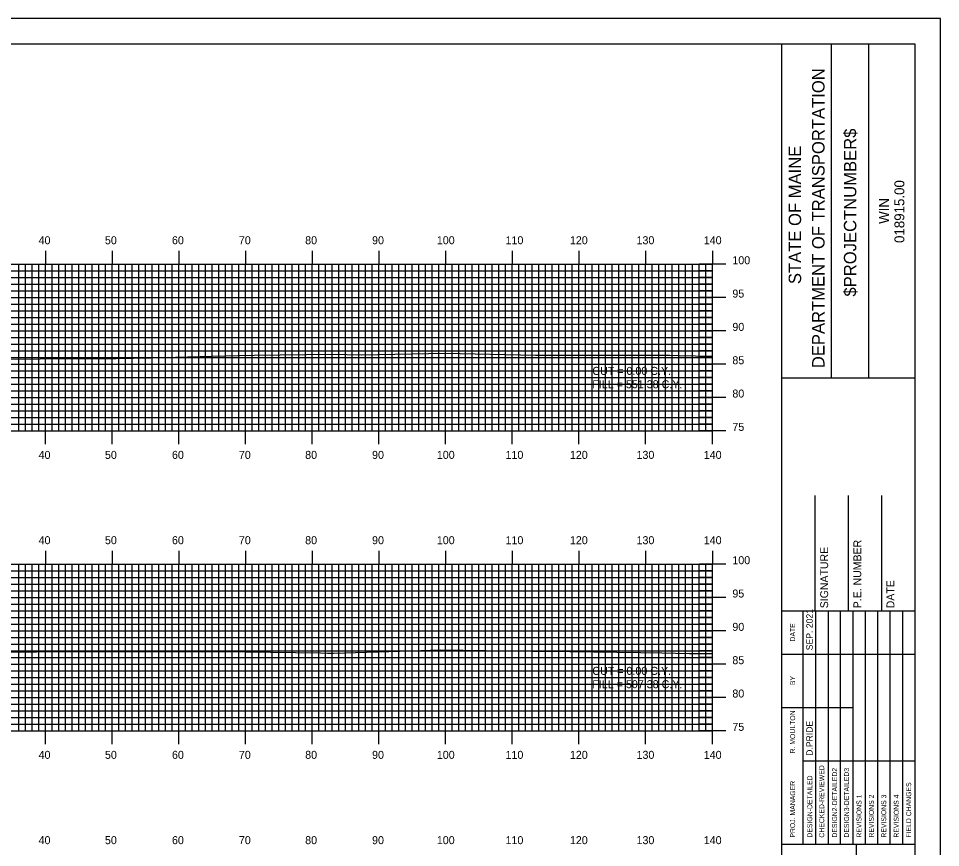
# Model space of a CAD drawing. Extents: x 1666 to 2009, y -1658 to -1438.
# Drawn here: x 1867.6 to 2005.9, y -1562.1 to -1437.7 of the extents above; entities that cross this region are included whole.
import ezdxf

# ---------------------------------------------------------------- set-up
doc = ezdxf.new("R2010")
doc.units = 0
for name, color, linetype in [('BORDER', 7, 'Continuous'), ('D_Text_Standard', 7, 'Continuous'), ('H_V ANNOTATION', 7, 'Continuous'), ('MAJOR', 7, 'Continuous'), ('MINOR', 7, 'Continuous'), ('PLOT BOUNDARY', 7, 'Continuous'), ('S_Roadway_Centerline', 7, 'Continuous')]:
    doc.layers.add(name, color=color, linetype=linetype)

msp = doc.modelspace()

# ---------------------------------------------------------------- linework, layer by layer
at = {"layer": 'BORDER'}
for p, q in [((1982.07, -1651.6), (1982.07, -1441.6)), ((1989.53, -1491.61), (1989.53, -1441.61)), ((1995.12, -1491.61), (1995.12, -1441.61)), ((1982.08, -1491.62), (2002.07, -1491.62)), ((1987.07, -1526.6), (1987.07, -1509.3)), ((1992.07, -1526.6), (1992.07, -1509.3)), ((1997.07, -1526.6), (1997.07, -1509.3)), ((1982.07, -1526.6), (2002.07, -1526.6)), ((1982.07, -1561.6), (2002.07, -1561.6)), ((1993.26, -1631.6), (1993.26, -1561.6))]:
    msp.add_line(p, q, dxfattribs=at)
msp.add_lwpolyline([(1682.07, -1651.6), (2002.07, -1651.6), (2002.07, -1441.6), (1682.07, -1441.6)], close=True, dxfattribs=at)
for points in [[(1985.3, -1533.1), (1985.3, -1526.6)], [(1987.17, -1561.59), (1987.17, -1526.6)], [(1989.03, -1526.6), (1989.03, -1561.59)], [(1990.9, -1561.59), (1990.9, -1526.6)], [(1992.76, -1561.59), (1992.76, -1526.6)], [(1994.62, -1561.59), (1994.62, -1526.6)], [(1996.49, -1561.59), (1996.49, -1526.6)], [(1998.35, -1561.59), (1998.35, -1526.6)], [(2000.21, -1561.59), (2000.21, -1526.6)], [(1985.31, -1561.59), (1985.31, -1528.01)], [(1982.07, -1533.1), (2002.07, -1533.1)], [(1982.07, -1541.1), (1985.31, -1541.1)], [(1985.3, -1541.1), (1992.76, -1541.1)], [(1985.3, -1549.1), (2002.07, -1549.1)]]:
    msp.add_lwpolyline(points, dxfattribs=at)
at = {"layer": 'MAJOR'}
for p, q in [((1871.67, -1472.6), (1871.67, -1474.6)), ((1881.67, -1472.6), (1881.67, -1474.6)), ((1891.67, -1472.6), (1891.67, -1474.6)), ((1901.67, -1472.6), (1901.67, -1474.6)), ((1911.67, -1472.6), (1911.67, -1474.6)), ((1921.67, -1472.6), (1921.67, -1474.6)), ((1931.67, -1472.6), (1931.67, -1474.6)), ((1941.67, -1472.6), (1941.67, -1474.6)), ((1951.67, -1472.6), (1951.67, -1474.6)), ((1961.67, -1472.6), (1961.67, -1474.6)), ((1971.67, -1472.6), (1971.67, -1474.6)), ((1691.67, -1474.6), (1971.67, -1474.6)), ((1691.67, -1474.6), (1971.67, -1474.6)), ((1871.67, -1499.6), (1871.67, -1474.6)), ((1881.67, -1499.6), (1881.67, -1474.6)), ((1891.67, -1499.6), (1891.67, -1474.6)), ((1901.67, -1499.6), (1901.67, -1474.6)), ((1911.67, -1499.6), (1911.67, -1474.6)), ((1921.67, -1499.6), (1921.67, -1474.6)), ((1931.67, -1499.6), (1931.67, -1474.6)), ((1941.67, -1499.6), (1941.67, -1474.6)), ((1951.67, -1499.6), (1951.67, -1474.6)), ((1961.67, -1499.6), (1961.67, -1474.6)), ((1973.68, -1474.6), (1969.67, -1474.6)), ((1971.67, -1499.6), (1971.67, -1474.6)), ((1971.67, -1499.6), (1971.67, -1474.6)), ((1691.67, -1479.6), (1971.67, -1479.6)), ((1973.68, -1479.6), (1969.67, -1479.6)), ((1691.67, -1484.6), (1971.67, -1484.6)), ((1973.68, -1484.6), (1969.67, -1484.6)), ((1691.67, -1489.6), (1971.67, -1489.6)), ((1973.68, -1489.6), (1969.67, -1489.6)), ((1691.67, -1494.6), (1971.67, -1494.6)), ((1973.68, -1494.6), (1969.67, -1494.6)), ((1691.67, -1499.6), (1971.67, -1499.6)), ((1691.67, -1499.6), (1971.67, -1499.6)), ((1871.67, -1501.61), (1871.67, -1499.6)), ((1881.67, -1501.61), (1881.67, -1499.6)), ((1891.67, -1501.61), (1891.67, -1499.6)), ((1901.67, -1501.61), (1901.67, -1499.6)), ((1911.67, -1501.61), (1911.67, -1499.6)), ((1921.67, -1501.61), (1921.67, -1499.6)), ((1931.67, -1501.61), (1931.67, -1499.6)), ((1941.67, -1501.61), (1941.67, -1499.6)), ((1951.67, -1501.61), (1951.67, -1499.6)), ((1961.67, -1501.61), (1961.67, -1499.6)), ((1973.68, -1499.6), (1969.67, -1499.6)), ((1971.67, -1501.61), (1971.67, -1499.6)), ((1871.67, -1517.6), (1871.67, -1519.6)), ((1881.67, -1517.6), (1881.67, -1519.6)), ((1891.67, -1517.6), (1891.67, -1519.6)), ((1901.67, -1517.6), (1901.67, -1519.6)), ((1911.67, -1517.6), (1911.67, -1519.6)), ((1921.67, -1517.6), (1921.67, -1519.6)), ((1931.67, -1517.6), (1931.67, -1519.6)), ((1941.67, -1517.6), (1941.67, -1519.6)), ((1951.67, -1517.6), (1951.67, -1519.6)), ((1961.67, -1517.6), (1961.67, -1519.6)), ((1971.67, -1517.6), (1971.67, -1519.6)), ((1691.67, -1519.6), (1971.67, -1519.6)), ((1691.67, -1519.6), (1971.67, -1519.6)), ((1871.67, -1544.6), (1871.67, -1519.6)), ((1881.67, -1544.6), (1881.67, -1519.6)), ((1891.67, -1544.6), (1891.67, -1519.6)), ((1901.67, -1544.6), (1901.67, -1519.6)), ((1911.67, -1544.6), (1911.67, -1519.6)), ((1921.67, -1544.6), (1921.67, -1519.6)), ((1931.67, -1544.6), (1931.67, -1519.6)), ((1941.67, -1544.6), (1941.67, -1519.6)), ((1951.67, -1544.6), (1951.67, -1519.6)), ((1961.67, -1544.6), (1961.67, -1519.6)), ((1973.68, -1519.6), (1969.67, -1519.6)), ((1971.67, -1544.6), (1971.67, -1519.6)), ((1971.67, -1544.6), (1971.67, -1519.6)), ((1691.67, -1524.6), (1971.67, -1524.6)), ((1973.68, -1524.6), (1969.67, -1524.6)), ((1691.67, -1529.6), (1971.67, -1529.6)), ((1973.68, -1529.6), (1969.67, -1529.6)), ((1691.67, -1534.6), (1971.67, -1534.6)), ((1973.68, -1534.6), (1969.67, -1534.6)), ((1691.67, -1539.6), (1971.67, -1539.6)), ((1973.68, -1539.6), (1969.67, -1539.6)), ((1691.67, -1544.6), (1971.67, -1544.6)), ((1691.67, -1544.6), (1971.67, -1544.6)), ((1871.67, -1546.61), (1871.67, -1544.6)), ((1881.67, -1546.61), (1881.67, -1544.6)), ((1891.67, -1546.61), (1891.67, -1544.6)), ((1901.67, -1546.61), (1901.67, -1544.6)), ((1911.67, -1546.61), (1911.67, -1544.6)), ((1921.67, -1546.61), (1921.67, -1544.6)), ((1931.67, -1546.61), (1931.67, -1544.6)), ((1941.67, -1546.61), (1941.67, -1544.6)), ((1951.67, -1546.61), (1951.67, -1544.6)), ((1961.67, -1546.61), (1961.67, -1544.6)), ((1973.68, -1544.6), (1969.67, -1544.6)), ((1971.67, -1546.61), (1971.67, -1544.6))]:
    msp.add_line(p, q, dxfattribs=at)
at = {"layer": 'MINOR'}
for p, q in [((1867.67, -1499.6), (1867.67, -1474.6)), ((1868.67, -1499.6), (1868.67, -1474.6)), ((1869.67, -1499.6), (1869.67, -1474.6)), ((1870.67, -1499.6), (1870.67, -1474.6)), ((1872.67, -1499.6), (1872.67, -1474.6)), ((1873.67, -1499.6), (1873.67, -1474.6)), ((1874.67, -1499.6), (1874.67, -1474.6)), ((1875.67, -1499.6), (1875.67, -1474.6)), ((1876.67, -1499.6), (1876.67, -1474.6)), ((1877.67, -1499.6), (1877.67, -1474.6)), ((1878.67, -1499.6), (1878.67, -1474.6)), ((1879.67, -1499.6), (1879.67, -1474.6)), ((1880.67, -1499.6), (1880.67, -1474.6)), ((1882.67, -1499.6), (1882.67, -1474.6)), ((1883.67, -1499.6), (1883.67, -1474.6)), ((1884.67, -1499.6), (1884.67, -1474.6)), ((1885.67, -1499.6), (1885.67, -1474.6)), ((1886.67, -1499.6), (1886.67, -1474.6)), ((1887.67, -1499.6), (1887.67, -1474.6)), ((1888.67, -1499.6), (1888.67, -1474.6)), ((1889.67, -1499.6), (1889.67, -1474.6)), ((1890.67, -1499.6), (1890.67, -1474.6)), ((1892.67, -1499.6), (1892.67, -1474.6)), ((1893.67, -1499.6), (1893.67, -1474.6)), ((1894.67, -1499.6), (1894.67, -1474.6)), ((1895.67, -1499.6), (1895.67, -1474.6)), ((1896.67, -1499.6), (1896.67, -1474.6)), ((1897.67, -1499.6), (1897.67, -1474.6)), ((1898.67, -1499.6), (1898.67, -1474.6)), ((1899.67, -1499.6), (1899.67, -1474.6)), ((1900.67, -1499.6), (1900.67, -1474.6)), ((1902.67, -1499.6), (1902.67, -1474.6)), ((1903.67, -1499.6), (1903.67, -1474.6)), ((1904.67, -1499.6), (1904.67, -1474.6)), ((1905.67, -1499.6), (1905.67, -1474.6)), ((1906.67, -1499.6), (1906.67, -1474.6)), ((1907.67, -1499.6), (1907.67, -1474.6)), ((1908.67, -1499.6), (1908.67, -1474.6)), ((1909.67, -1499.6), (1909.67, -1474.6)), ((1910.67, -1499.6), (1910.67, -1474.6)), ((1912.67, -1499.6), (1912.67, -1474.6)), ((1913.67, -1499.6), (1913.67, -1474.6)), ((1914.67, -1499.6), (1914.67, -1474.6)), ((1915.67, -1499.6), (1915.67, -1474.6)), ((1916.67, -1499.6), (1916.67, -1474.6)), ((1917.67, -1499.6), (1917.67, -1474.6)), ((1918.67, -1499.6), (1918.67, -1474.6)), ((1919.67, -1499.6), (1919.67, -1474.6)), ((1920.67, -1499.6), (1920.67, -1474.6)), ((1922.67, -1499.6), (1922.67, -1474.6)), ((1923.67, -1499.6), (1923.67, -1474.6)), ((1924.67, -1499.6), (1924.67, -1474.6)), ((1925.67, -1499.6), (1925.67, -1474.6)), ((1926.67, -1499.6), (1926.67, -1474.6)), ((1927.67, -1499.6), (1927.67, -1474.6)), ((1928.67, -1499.6), (1928.67, -1474.6)), ((1929.67, -1499.6), (1929.67, -1474.6)), ((1930.67, -1499.6), (1930.67, -1474.6)), ((1932.67, -1499.6), (1932.67, -1474.6)), ((1933.67, -1499.6), (1933.67, -1474.6)), ((1934.67, -1499.6), (1934.67, -1474.6)), ((1935.67, -1499.6), (1935.67, -1474.6)), ((1936.67, -1499.6), (1936.67, -1474.6)), ((1937.67, -1499.6), (1937.67, -1474.6)), ((1938.67, -1499.6), (1938.67, -1474.6)), ((1939.67, -1499.6), (1939.67, -1474.6)), ((1940.67, -1499.6), (1940.67, -1474.6)), ((1942.67, -1499.6), (1942.67, -1474.6)), ((1943.67, -1499.6), (1943.67, -1474.6)), ((1944.67, -1499.6), (1944.67, -1474.6)), ((1945.67, -1499.6), (1945.67, -1474.6)), ((1946.67, -1499.6), (1946.67, -1474.6)), ((1947.67, -1499.6), (1947.67, -1474.6)), ((1948.67, -1499.6), (1948.67, -1474.6)), ((1949.67, -1499.6), (1949.67, -1474.6)), ((1950.67, -1499.6), (1950.67, -1474.6)), ((1952.67, -1499.6), (1952.67, -1474.6)), ((1953.67, -1499.6), (1953.67, -1474.6)), ((1954.67, -1499.6), (1954.67, -1474.6)), ((1955.67, -1499.6), (1955.67, -1474.6)), ((1956.67, -1499.6), (1956.67, -1474.6)), ((1957.67, -1499.6), (1957.67, -1474.6)), ((1958.67, -1499.6), (1958.67, -1474.6)), ((1959.67, -1499.6), (1959.67, -1474.6)), ((1960.67, -1499.6), (1960.67, -1474.6)), ((1962.67, -1499.6), (1962.67, -1474.6)), ((1963.67, -1499.6), (1963.67, -1474.6)), ((1964.67, -1499.6), (1964.67, -1474.6)), ((1965.67, -1499.6), (1965.67, -1474.6)), ((1966.67, -1499.6), (1966.67, -1474.6)), ((1967.67, -1499.6), (1967.67, -1474.6)), ((1968.67, -1499.6), (1968.67, -1474.6)), ((1969.67, -1499.6), (1969.67, -1474.6)), ((1970.67, -1499.6), (1970.67, -1474.6)), ((1691.67, -1475.6), (1971.67, -1475.6)), ((1971.67, -1475.6), (1969.67, -1475.6)), ((1691.67, -1476.6), (1971.67, -1476.6)), ((1691.67, -1477.6), (1971.67, -1477.6)), ((1971.67, -1476.6), (1969.67, -1476.6)), ((1971.67, -1477.6), (1969.67, -1477.6)), ((1691.67, -1478.6), (1971.67, -1478.6)), ((1971.67, -1478.6), (1969.67, -1478.6)), ((1691.67, -1480.6), (1971.67, -1480.6)), ((1971.67, -1480.6), (1969.67, -1480.6)), ((1691.67, -1481.6), (1971.67, -1481.6)), ((1971.67, -1481.6), (1969.67, -1481.6)), ((1691.67, -1482.6), (1971.67, -1482.6)), ((1971.67, -1482.6), (1969.67, -1482.6)), ((1691.67, -1483.6), (1971.67, -1483.6)), ((1971.67, -1483.6), (1969.67, -1483.6)), ((1691.67, -1485.6), (1971.67, -1485.6)), ((1971.67, -1485.6), (1969.67, -1485.6)), ((1691.67, -1486.6), (1971.67, -1486.6)), ((1691.67, -1487.6), (1971.67, -1487.6)), ((1971.67, -1486.6), (1969.67, -1486.6)), ((1971.67, -1487.6), (1969.67, -1487.6)), ((1691.67, -1488.6), (1971.67, -1488.6)), ((1971.67, -1488.6), (1969.67, -1488.6)), ((1691.67, -1490.6), (1971.67, -1490.6)), ((1691.67, -1491.6), (1971.67, -1491.6)), ((1971.67, -1490.6), (1969.67, -1490.6)), ((1971.67, -1491.6), (1969.67, -1491.6)), ((1691.67, -1492.6), (1971.67, -1492.6)), ((1971.67, -1492.6), (1969.67, -1492.6)), ((1691.67, -1493.6), (1971.67, -1493.6)), ((1971.67, -1493.6), (1969.67, -1493.6)), ((1691.67, -1495.6), (1971.67, -1495.6)), ((1971.67, -1495.6), (1969.67, -1495.6)), ((1691.67, -1496.6), (1971.67, -1496.6)), ((1971.67, -1496.6), (1969.67, -1496.6)), ((1691.67, -1497.6), (1971.67, -1497.6)), ((1691.67, -1498.6), (1971.67, -1498.6)), ((1971.67, -1497.6), (1969.67, -1497.6)), ((1971.67, -1498.6), (1969.67, -1498.6)), ((1691.67, -1520.6), (1971.67, -1520.6)), ((1867.67, -1544.6), (1867.67, -1519.6)), ((1868.67, -1544.6), (1868.67, -1519.6)), ((1869.67, -1544.6), (1869.67, -1519.6)), ((1870.67, -1544.6), (1870.67, -1519.6)), ((1872.67, -1544.6), (1872.67, -1519.6)), ((1873.67, -1544.6), (1873.67, -1519.6)), ((1874.67, -1544.6), (1874.67, -1519.6)), ((1875.67, -1544.6), (1875.67, -1519.6)), ((1876.67, -1544.6), (1876.67, -1519.6)), ((1877.67, -1544.6), (1877.67, -1519.6)), ((1878.67, -1544.6), (1878.67, -1519.6)), ((1879.67, -1544.6), (1879.67, -1519.6)), ((1880.67, -1544.6), (1880.67, -1519.6)), ((1882.67, -1544.6), (1882.67, -1519.6)), ((1883.67, -1544.6), (1883.67, -1519.6)), ((1884.67, -1544.6), (1884.67, -1519.6)), ((1885.67, -1544.6), (1885.67, -1519.6)), ((1886.67, -1544.6), (1886.67, -1519.6)), ((1887.67, -1544.6), (1887.67, -1519.6)), ((1888.67, -1544.6), (1888.67, -1519.6)), ((1889.67, -1544.6), (1889.67, -1519.6)), ((1890.67, -1544.6), (1890.67, -1519.6)), ((1892.67, -1544.6), (1892.67, -1519.6)), ((1893.67, -1544.6), (1893.67, -1519.6)), ((1894.67, -1544.6), (1894.67, -1519.6)), ((1895.67, -1544.6), (1895.67, -1519.6)), ((1896.67, -1544.6), (1896.67, -1519.6)), ((1897.67, -1544.6), (1897.67, -1519.6)), ((1898.67, -1544.6), (1898.67, -1519.6)), ((1899.67, -1544.6), (1899.67, -1519.6)), ((1900.67, -1544.6), (1900.67, -1519.6)), ((1902.67, -1544.6), (1902.67, -1519.6)), ((1903.67, -1544.6), (1903.67, -1519.6)), ((1904.67, -1544.6), (1904.67, -1519.6)), ((1905.67, -1544.6), (1905.67, -1519.6)), ((1906.67, -1544.6), (1906.67, -1519.6)), ((1907.67, -1544.6), (1907.67, -1519.6)), ((1908.67, -1544.6), (1908.67, -1519.6)), ((1909.67, -1544.6), (1909.67, -1519.6)), ((1910.67, -1544.6), (1910.67, -1519.6)), ((1912.67, -1544.6), (1912.67, -1519.6)), ((1913.67, -1544.6), (1913.67, -1519.6)), ((1914.67, -1544.6), (1914.67, -1519.6)), ((1915.67, -1544.6), (1915.67, -1519.6)), ((1916.67, -1544.6), (1916.67, -1519.6)), ((1917.67, -1544.6), (1917.67, -1519.6)), ((1918.67, -1544.6), (1918.67, -1519.6)), ((1919.67, -1544.6), (1919.67, -1519.6)), ((1920.67, -1544.6), (1920.67, -1519.6)), ((1922.67, -1544.6), (1922.67, -1519.6)), ((1923.67, -1544.6), (1923.67, -1519.6)), ((1924.67, -1544.6), (1924.67, -1519.6)), ((1925.67, -1544.6), (1925.67, -1519.6)), ((1926.67, -1544.6), (1926.67, -1519.6)), ((1927.67, -1544.6), (1927.67, -1519.6)), ((1928.67, -1544.6), (1928.67, -1519.6)), ((1929.67, -1544.6), (1929.67, -1519.6)), ((1930.67, -1544.6), (1930.67, -1519.6)), ((1932.67, -1544.6), (1932.67, -1519.6)), ((1933.67, -1544.6), (1933.67, -1519.6)), ((1934.67, -1544.6), (1934.67, -1519.6)), ((1935.67, -1544.6), (1935.67, -1519.6)), ((1936.67, -1544.6), (1936.67, -1519.6)), ((1937.67, -1544.6), (1937.67, -1519.6)), ((1938.67, -1544.6), (1938.67, -1519.6)), ((1939.67, -1544.6), (1939.67, -1519.6)), ((1940.67, -1544.6), (1940.67, -1519.6)), ((1942.67, -1544.6), (1942.67, -1519.6)), ((1943.67, -1544.6), (1943.67, -1519.6)), ((1944.67, -1544.6), (1944.67, -1519.6)), ((1945.67, -1544.6), (1945.67, -1519.6)), ((1946.67, -1544.6), (1946.67, -1519.6)), ((1947.67, -1544.6), (1947.67, -1519.6)), ((1948.67, -1544.6), (1948.67, -1519.6)), ((1949.67, -1544.6), (1949.67, -1519.6)), ((1950.67, -1544.6), (1950.67, -1519.6)), ((1952.67, -1544.6), (1952.67, -1519.6)), ((1953.67, -1544.6), (1953.67, -1519.6)), ((1954.67, -1544.6), (1954.67, -1519.6)), ((1955.67, -1544.6), (1955.67, -1519.6)), ((1956.67, -1544.6), (1956.67, -1519.6)), ((1957.67, -1544.6), (1957.67, -1519.6)), ((1958.67, -1544.6), (1958.67, -1519.6)), ((1959.67, -1544.6), (1959.67, -1519.6)), ((1960.67, -1544.6), (1960.67, -1519.6)), ((1962.67, -1544.6), (1962.67, -1519.6)), ((1963.67, -1544.6), (1963.67, -1519.6)), ((1964.67, -1544.6), (1964.67, -1519.6)), ((1965.67, -1544.6), (1965.67, -1519.6)), ((1966.67, -1544.6), (1966.67, -1519.6)), ((1967.67, -1544.6), (1967.67, -1519.6)), ((1968.67, -1544.6), (1968.67, -1519.6)), ((1969.67, -1544.6), (1969.67, -1519.6)), ((1971.67, -1520.6), (1969.67, -1520.6)), ((1970.67, -1544.6), (1970.67, -1519.6)), ((1691.67, -1521.6), (1971.67, -1521.6)), ((1971.67, -1521.6), (1969.67, -1521.6)), ((1691.67, -1522.6), (1971.67, -1522.6)), ((1971.67, -1522.6), (1969.67, -1522.6)), ((1691.67, -1523.6), (1971.67, -1523.6)), ((1971.67, -1523.6), (1969.67, -1523.6)), ((1691.67, -1525.6), (1971.67, -1525.6)), ((1971.67, -1525.6), (1969.67, -1525.6)), ((1691.67, -1526.6), (1971.67, -1526.6)), ((1691.67, -1527.6), (1971.67, -1527.6)), ((1971.67, -1526.6), (1969.67, -1526.6)), ((1971.67, -1527.6), (1969.67, -1527.6)), ((1691.67, -1528.6), (1971.67, -1528.6)), ((1971.67, -1528.6), (1969.67, -1528.6)), ((1691.67, -1530.6), (1971.67, -1530.6)), ((1691.67, -1531.6), (1971.67, -1531.6)), ((1971.67, -1530.6), (1969.67, -1530.6)), ((1971.67, -1531.6), (1969.67, -1531.6)), ((1691.67, -1532.6), (1971.67, -1532.6)), ((1971.67, -1532.6), (1969.67, -1532.6)), ((1691.67, -1533.6), (1971.67, -1533.6)), ((1971.67, -1533.6), (1969.67, -1533.6)), ((1691.67, -1535.6), (1971.67, -1535.6)), ((1971.67, -1535.6), (1969.67, -1535.6)), ((1691.67, -1536.6), (1971.67, -1536.6)), ((1971.67, -1536.6), (1969.67, -1536.6)), ((1691.67, -1537.6), (1971.67, -1537.6)), ((1691.67, -1538.6), (1971.67, -1538.6)), ((1971.67, -1537.6), (1969.67, -1537.6)), ((1971.67, -1538.6), (1969.67, -1538.6)), ((1691.67, -1540.6), (1971.67, -1540.6)), ((1971.67, -1540.6), (1969.67, -1540.6)), ((1691.67, -1541.6), (1971.67, -1541.6)), ((1691.67, -1542.6), (1971.67, -1542.6)), ((1971.67, -1541.6), (1969.67, -1541.6)), ((1971.67, -1542.6), (1969.67, -1542.6)), ((1691.67, -1543.6), (1971.67, -1543.6)), ((1971.67, -1543.6), (1969.67, -1543.6))]:
    msp.add_line(p, q, dxfattribs=at)
at = {"layer": 'PLOT BOUNDARY'}
msp.add_lwpolyline([(1665.89, -1657.72), (2005.89, -1657.72), (2005.89, -1437.72), (1665.89, -1437.72)], close=True, dxfattribs=at)
at = {"layer": 'S_Roadway_Centerline'}
for points in [[(1865.49, -1488.85), (1876.3, -1488.74), (1882.3, -1488.76), (1887.5, -1488.63), (1898.57, -1488.34), (1902.98, -1488.23), (1914.71, -1488.11), (1919.02, -1488.17), (1931.59, -1487.94), (1945.18, -1488.26), (1947.71, -1488.26), (1950.14, -1488.25), (1965.24, -1488.25), (1966.61, -1488.27), (1971.67, -1488.4)], [(1864.78, -1532.81), (1875.82, -1532.7), (1880.7, -1532.68), (1895.25, -1532.73), (1897.92, -1532.72), (1912.93, -1532.92), (1913.99, -1532.95), (1914.85, -1532.93), (1926.48, -1532.58), (1930.91, -1532.45), (1944.62, -1532.64), (1946.74, -1532.64), (1960.9, -1532.87), (1964.12, -1532.89), (1968.23, -1533.01), (1971.67, -1533.01)]]:
    msp.add_lwpolyline(points, dxfattribs=at)

# ---------------------------------------------------------------- texts
at = {"layer": 'BORDER'}
for s, height, p in [('DEPARTMENT OF TRANSPORTATION', 1.8635, (1988.49, -1490.19)), ('$PROJECTNUMBER$', 1.8635, (1993.26, -1479.45)), ('STATE OF MAINE', 1.8635, (1984.98, -1477.58)), ('018915.00', 1.491, (2000.46, -1471.41)), ('WIN', 1.491, (1998.15, -1468.54)), ('P.E. NUMBER', 1.1811, (1994, -1526.21)), ('SIGNATURE', 1.181, (1989.03, -1526.21)), ('DATE', 1.181, (1998.96, -1526.21)), ('SEP. 2021', 0.969, (1986.72, -1532.51)), ('DATE', 0.743, (1984.08, -1531.19)), ('BY', 0.743, (1984.08, -1537.73)), ('R. MOULTON', 0.745, (1984.08, -1547.99)), ('D.PRIDE', 0.969, (1986.72, -1548.35)), ('CHECKED-REVIEWED', 0.7455, (1988.44, -1560.62)), ('DESIGN2-DETAILED2', 0.7455, (1990.37, -1560.62)), ('DESIGN3-DETAILED3', 0.7455, (1992.16, -1560.62)), ('PROJ. MANAGER', 0.7455, (1984.08, -1560.62)), ('DESIGN-DETAILED', 0.7455, (1986.65, -1560.62)), ('FIELD CHANGES', 0.7455, (2001.48, -1560.62)), ('REVISIONS 1', 0.7455, (1994.03, -1560.62)), ('REVISIONS 2', 0.7455, (1995.89, -1560.62)), ('REVISIONS 3', 0.7455, (1997.75, -1560.62)), ('REVISIONS 4', 0.7455, (1999.62, -1560.62))]:
    msp.add_text(s, height=height, rotation=90, dxfattribs=at).set_placement(p)
at = {"layer": 'D_Text_Standard'}
for s, p in [('CUT = 0.00 C.Y.', (1953.67, -1491.2)), ('FILL = 551.38 C.Y.', (1953.67, -1493.2)), ('CUT = 0.00 C.Y.', (1953.67, -1536.2)), ('FILL = 507.38 C.Y.', (1953.67, -1538.2))]:
    msp.add_text(s, height=1.2, dxfattribs=at).set_placement(p)
at = {"layer": 'H_V ANNOTATION'}
for s, p in [('40', (1870.65, -1471.6)), ('50', (1880.6, -1471.6)), ('60', (1890.65, -1471.6)), ('70', (1900.68, -1471.6)), ('80', (1910.62, -1471.6)), ('90', (1920.65, -1471.6)), ('100', (1930.36, -1471.6)), ('110', (1940.66, -1471.6)), ('120', (1950.31, -1471.6)), ('130', (1960.3, -1471.6)), ('140', (1970.38, -1471.6)), ('100', (1974.67, -1474.6)), ('95', (1974.67, -1479.6)), ('90', (1974.67, -1484.6)), ('85', (1974.67, -1489.6)), ('80', (1974.67, -1494.6)), ('75', (1974.67, -1499.6)), ('40', (1870.65, -1503.8)), ('50', (1880.6, -1503.8)), ('60', (1890.65, -1503.8)), ('70', (1900.68, -1503.8)), ('80', (1910.62, -1503.8)), ('90', (1920.65, -1503.8)), ('100', (1930.36, -1503.8)), ('110', (1940.66, -1503.8)), ('120', (1950.31, -1503.8)), ('130', (1960.3, -1503.8)), ('140', (1970.38, -1503.8)), ('40', (1870.65, -1516.6)), ('50', (1880.6, -1516.6)), ('60', (1890.65, -1516.6)), ('70', (1900.68, -1516.6)), ('80', (1910.62, -1516.6)), ('90', (1920.65, -1516.6)), ('100', (1930.36, -1516.6)), ('110', (1940.66, -1516.6)), ('120', (1950.31, -1516.6)), ('130', (1960.3, -1516.6)), ('140', (1970.38, -1516.6)), ('100', (1974.67, -1519.6)), ('95', (1974.67, -1524.6)), ('90', (1974.67, -1529.6)), ('85', (1974.67, -1534.6)), ('80', (1974.67, -1539.6)), ('75', (1974.67, -1544.6)), ('40', (1870.65, -1548.8)), ('50', (1880.6, -1548.8)), ('60', (1890.65, -1548.8)), ('70', (1900.68, -1548.8)), ('80', (1910.62, -1548.8)), ('90', (1920.65, -1548.8)), ('100', (1930.36, -1548.8)), ('110', (1940.66, -1548.8)), ('120', (1950.31, -1548.8)), ('130', (1960.3, -1548.8)), ('140', (1970.38, -1548.8)), ('40', (1870.65, -1561.6)), ('50', (1880.6, -1561.6)), ('60', (1890.65, -1561.6)), ('70', (1900.68, -1561.6)), ('80', (1910.62, -1561.6)), ('90', (1920.65, -1561.6)), ('100', (1930.36, -1561.6)), ('110', (1940.66, -1561.6)), ('120', (1950.31, -1561.6)), ('130', (1960.3, -1561.6)), ('140', (1970.38, -1561.6))]:
    msp.add_text(s, height=1.2, dxfattribs=at).set_placement(p)

doc.saveas('drawing.dxf')
